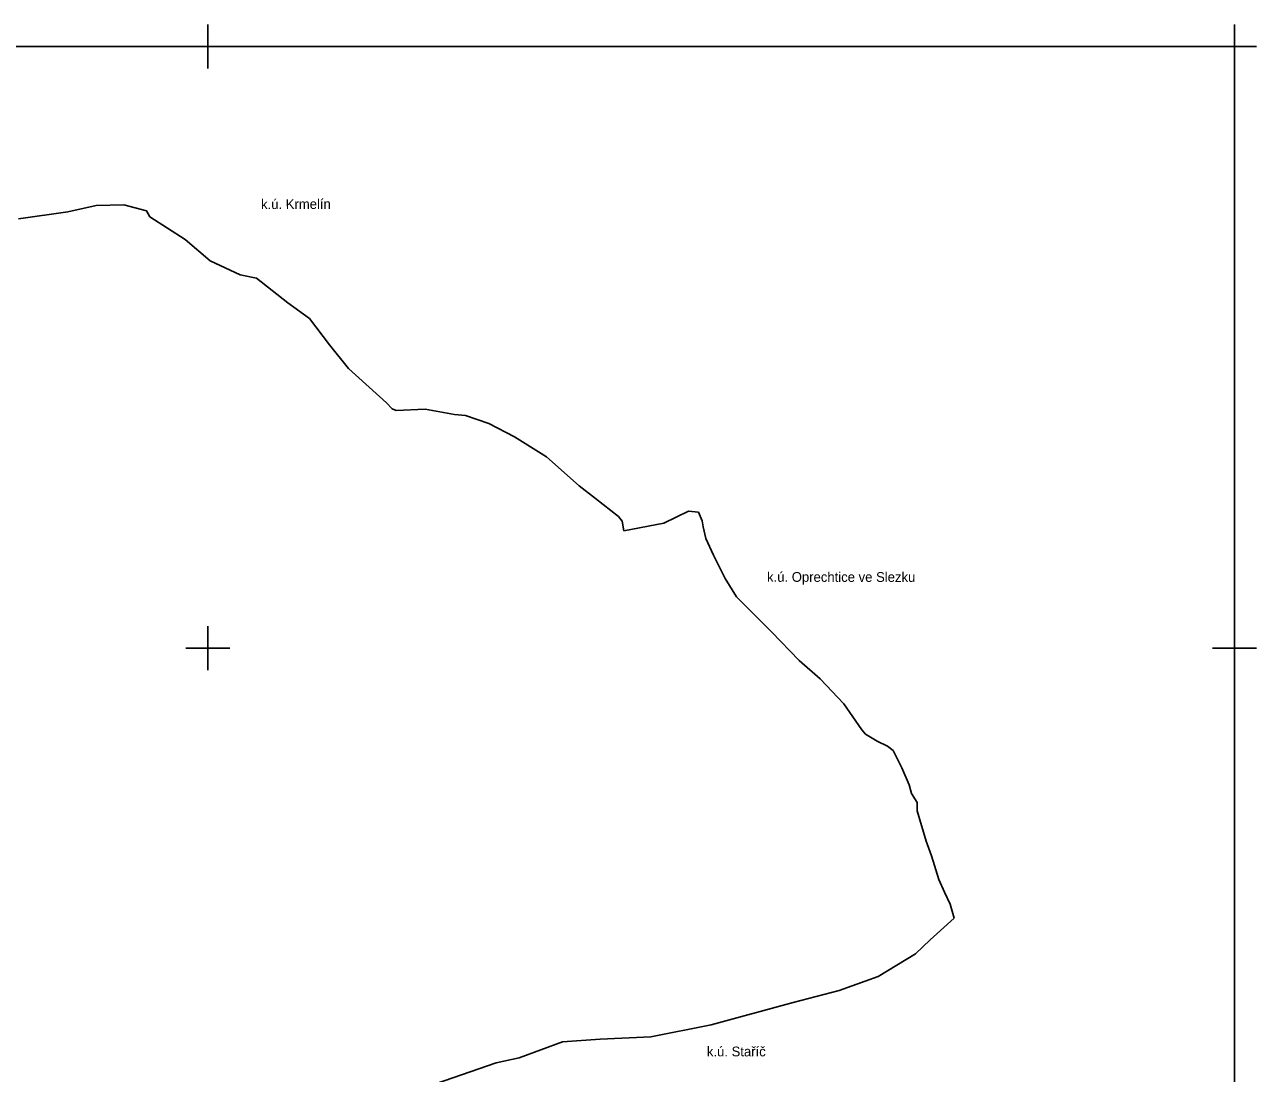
# Model space of a CAD drawing. Extents: x -478440 to -472455, y -1118045 to -1113755.
# Drawn here: x -474975 to -472455, y -1115900 to -1113755 of the extents above; entities that cross this region are included whole.
import ezdxf

# ---------------------------------------------------------------- set-up
doc = ezdxf.new("R2010")
doc.units = 0
for name, color, linetype in [('hranice kú', 7, 'Continuous'), ('Implicitní', 7, 'Continuous'), ('ObPÚ', 7, 'Continuous'), ('okolní k_ú_', 7, 'Continuous')]:
    doc.layers.add(name, color=color, linetype=linetype)

msp = doc.modelspace()

# ---------------------------------------------------------------- linework, layer by layer
at = {"layer": 'hranice kú'}
for p, q in [((-474886, -1114137.7), (-474987.2, -1114152.5)), ((-474828.5, -1114124.9), (-474886, -1114137.7)), ((-474772, -1114123.9), (-474828.5, -1114124.9)), ((-474725.6, -1114136), (-474772, -1114123.9)), ((-474718.2, -1114148.1), (-474725.6, -1114136)), ((-474646.3, -1114194.8), (-474718.2, -1114148.1)), ((-474595.2, -1114238.2), (-474646.3, -1114194.8)), ((-474533.5, -1114266.7), (-474595.2, -1114238.2)), ((-474500.2, -1114273.4), (-474533.5, -1114266.7)), ((-474436, -1114323.8), (-474500.2, -1114273.4)), ((-474392.1, -1114355.8), (-474436, -1114323.8)), ((-474351.1, -1114410.2), (-474392.1, -1114355.8)), ((-474312.1, -1114458.1), (-474351.1, -1114410.2)), ((-474234.1, -1114528.4), (-474312.1, -1114458.1)), ((-474222.7, -1114541.2), (-474234.1, -1114528.4)), ((-474214.6, -1114544.2), (-474222.7, -1114541.2)), ((-474155.1, -1114541.5), (-474214.6, -1114544.2)), ((-474095.2, -1114552.2), (-474155.1, -1114541.5)), ((-474072.7, -1114554.2), (-474095.2, -1114552.2)), ((-474025.3, -1114571.1), (-474072.7, -1114554.2)), ((-473972.5, -1114598), (-474025.3, -1114571.1)), ((-473907.3, -1114639), (-473972.5, -1114598)), ((-473840.6, -1114698.6), (-473907.3, -1114639)), ((-473807, -1114724.1), (-473840.6, -1114698.6)), ((-473760, -1114761.1), (-473807, -1114724.1)), ((-473752.6, -1114770.7), (-473760, -1114761.1)), ((-473616.5, -1114749.9), (-473666.9, -1114774.4)), ((-473595.9, -1114752.2), (-473616.5, -1114749.9)), ((-473588.6, -1114770.3), (-473595.9, -1114752.2)), ((-473748.8, -1114790.3), (-473752.6, -1114770.7)), ((-473666.9, -1114774.4), (-473748.8, -1114790.3)), ((-473587, -1114782.1), (-473588.6, -1114770.3)), ((-473581.1, -1114806.2), (-473587, -1114782.1)), ((-473565.4, -1114840.2), (-473581.1, -1114806.2)), ((-473541.9, -1114887.9), (-473565.4, -1114840.2)), ((-473518.4, -1114925.3), (-473541.9, -1114887.9)), ((-473447.1, -1114996.9), (-473518.4, -1114925.3)), ((-473390.3, -1115055.8), (-473447.1, -1114996.9)), ((-473347.2, -1115093.3), (-473390.3, -1115055.8)), ((-473299.1, -1115144.4), (-473347.2, -1115093.3)), ((-473261.8, -1115197.2), (-473299.1, -1115144.4)), ((-473254.4, -1115206.6), (-473261.8, -1115197.2)), ((-473230.6, -1115220.7), (-473254.4, -1115206.6)), ((-473209.4, -1115230.8), (-473230.6, -1115220.7)), ((-473197.9, -1115239.5), (-473209.4, -1115230.8)), ((-473191.9, -1115251.7), (-473197.9, -1115239.5)), ((-473180.1, -1115275.5), (-473191.9, -1115251.7)), ((-473165, -1115309.9), (-473180.1, -1115275.5)), ((-473160.6, -1115327.4), (-473165, -1115309.9)), ((-473148.9, -1115345.9), (-473160.6, -1115327.4)), ((-473149.2, -1115363.1), (-473148.9, -1115345.9)), ((-473130.7, -1115424.9), (-473149.2, -1115363.1)), ((-473119.6, -1115455.5), (-473130.7, -1115424.9)), ((-473104.5, -1115503.7), (-473119.6, -1115455.5)), ((-473092.7, -1115529.3), (-473104.5, -1115503.7)), ((-473081.3, -1115554.2), (-473092.7, -1115529.3)), ((-473073.6, -1115582.8), (-473081.3, -1115554.2)), ((-473122.6, -1115627.2), (-473073.6, -1115582.8)), ((-473152.2, -1115655.7), (-473122.6, -1115627.2)), ((-473228.9, -1115701.8), (-473152.2, -1115655.7)), ((-473308.3, -1115730.5), (-473228.9, -1115701.8)), ((-473402.8, -1115755.4), (-473308.3, -1115730.5)), ((-473570.6, -1115801.1), (-473402.8, -1115755.4)), ((-473693.7, -1115825.7), (-473570.6, -1115801.1)), ((-473797.2, -1115830.4), (-473693.7, -1115825.7)), ((-473963.2, -1115868.4), (-473874.4, -1115835.4)), ((-473874.4, -1115835.4), (-473797.2, -1115830.4)), ((-474010.2, -1115878.5), (-473963.2, -1115868.4)), ((-474134.2, -1115921.7), (-474010.2, -1115878.5))]:
    msp.add_line(p, q, dxfattribs=at)
at = {"layer": 'Implicitní'}
for p, q in [((-474600.1, -1113755.1), (-474600.1, -1113845.1)), ((-474600.1, -1113755.1), (-474600.1, -1113845.1)), ((-474600.1, -1113755.1), (-474600.1, -1113845.1)), ((-474600.1, -1113755.1), (-474600.1, -1113845.1)), ((-474600.1, -1113755.1), (-474600.1, -1113845.1)), ((-474600.1, -1113755.1), (-474600.1, -1113845.1)), ((-474600.1, -1113755.1), (-474600.1, -1113845.1)), ((-474600.1, -1113755.1), (-474600.1, -1113845.1)), ((-474600.1, -1113755.1), (-474600.1, -1113845.1)), ((-474600.1, -1113755.1), (-474600.1, -1113845.1)), ((-474600.1, -1113755.1), (-474600.1, -1113845.1)), ((-474600.1, -1113755.1), (-474600.1, -1113845.1)), ((-472500.1, -1113755.1), (-472500.1, -1113845.1)), ((-472500.1, -1113755.1), (-472500.1, -1113845.1)), ((-472500.1, -1113755.1), (-472500.1, -1113845.1)), ((-472500.1, -1113755.1), (-472500.1, -1113845.1)), ((-474555.1, -1113800.1), (-474645.1, -1113800.1)), ((-474555.1, -1113800.1), (-474645.1, -1113800.1)), ((-474555.1, -1113800.1), (-474645.1, -1113800.1)), ((-474555.1, -1113800.1), (-474645.1, -1113800.1)), ((-474555.1, -1113800.1), (-474645.1, -1113800.1)), ((-474555.1, -1113800.1), (-474645.1, -1113800.1)), ((-474555.1, -1113800.1), (-474645.1, -1113800.1)), ((-474555.1, -1113800.1), (-474645.1, -1113800.1)), ((-474555.1, -1113800.1), (-474645.1, -1113800.1)), ((-474555.1, -1113800.1), (-474645.1, -1113800.1)), ((-474555.1, -1113800.1), (-474645.1, -1113800.1)), ((-474555.1, -1113800.1), (-474645.1, -1113800.1)), ((-472455.1, -1113800.1), (-472545.1, -1113800.1)), ((-472455.1, -1113800.1), (-472545.1, -1113800.1)), ((-472455.1, -1113800.1), (-472545.1, -1113800.1)), ((-472455.1, -1113800.1), (-472545.1, -1113800.1)), ((-474600.1, -1114985.1), (-474600.1, -1115075.1)), ((-474600.1, -1114985.1), (-474600.1, -1115075.1)), ((-474600.1, -1114985.1), (-474600.1, -1115075.1)), ((-474600.1, -1114985.1), (-474600.1, -1115075.1)), ((-474600.1, -1114985.1), (-474600.1, -1115075.1)), ((-474600.1, -1114985.1), (-474600.1, -1115075.1)), ((-474600.1, -1114985.1), (-474600.1, -1115075.1)), ((-474600.1, -1114985.1), (-474600.1, -1115075.1)), ((-474600.1, -1114985.1), (-474600.1, -1115075.1)), ((-474600.1, -1114985.1), (-474600.1, -1115075.1)), ((-474600.1, -1114985.1), (-474600.1, -1115075.1)), ((-474600.1, -1114985.1), (-474600.1, -1115075.1)), ((-474600.1, -1114985.1), (-474600.1, -1115075.1)), ((-474600.1, -1114985.1), (-474600.1, -1115075.1)), ((-474600.1, -1114985.1), (-474600.1, -1115075.1)), ((-474600.1, -1114985.1), (-474600.1, -1115075.1)), ((-474600.1, -1114985.1), (-474600.1, -1115075.1)), ((-474600.1, -1114985.1), (-474600.1, -1115075.1)), ((-474600.1, -1114985.1), (-474600.1, -1115075.1)), ((-474600.1, -1114985.1), (-474600.1, -1115075.1)), ((-472500.1, -1114985.1), (-472500.1, -1115075.1)), ((-472500.1, -1114985.1), (-472500.1, -1115075.1)), ((-472500.1, -1114985.1), (-472500.1, -1115075.1)), ((-472500.1, -1114985.1), (-472500.1, -1115075.1)), ((-472500.1, -1114985.1), (-472500.1, -1115075.1)), ((-472500.1, -1114985.1), (-472500.1, -1115075.1)), ((-472500.1, -1114985.1), (-472500.1, -1115075.1)), ((-472500.1, -1114985.1), (-472500.1, -1115075.1)), ((-472500.1, -1114985.1), (-472500.1, -1115075.1)), ((-472500.1, -1114985.1), (-472500.1, -1115075.1)), ((-474555.1, -1115030.1), (-474645.1, -1115030.1)), ((-474555.1, -1115030.1), (-474645.1, -1115030.1)), ((-474555.1, -1115030.1), (-474645.1, -1115030.1)), ((-474555.1, -1115030.1), (-474645.1, -1115030.1)), ((-474555.1, -1115030.1), (-474645.1, -1115030.1)), ((-474555.1, -1115030.1), (-474645.1, -1115030.1)), ((-474555.1, -1115030.1), (-474645.1, -1115030.1)), ((-474555.1, -1115030.1), (-474645.1, -1115030.1)), ((-474555.1, -1115030.1), (-474645.1, -1115030.1)), ((-474555.1, -1115030.1), (-474645.1, -1115030.1)), ((-474555.1, -1115030.1), (-474645.1, -1115030.1)), ((-474555.1, -1115030.1), (-474645.1, -1115030.1)), ((-474555.1, -1115030.1), (-474645.1, -1115030.1)), ((-474555.1, -1115030.1), (-474645.1, -1115030.1)), ((-474555.1, -1115030.1), (-474645.1, -1115030.1)), ((-474555.1, -1115030.1), (-474645.1, -1115030.1)), ((-474555.1, -1115030.1), (-474645.1, -1115030.1)), ((-474555.1, -1115030.1), (-474645.1, -1115030.1)), ((-474555.1, -1115030.1), (-474645.1, -1115030.1)), ((-474555.1, -1115030.1), (-474645.1, -1115030.1)), ((-472455.1, -1115030.1), (-472545.1, -1115030.1)), ((-472455.1, -1115030.1), (-472545.1, -1115030.1)), ((-472455.1, -1115030.1), (-472545.1, -1115030.1)), ((-472455.1, -1115030.1), (-472545.1, -1115030.1)), ((-472455.1, -1115030.1), (-472545.1, -1115030.1)), ((-472455.1, -1115030.1), (-472545.1, -1115030.1)), ((-472455.1, -1115030.1), (-472545.1, -1115030.1)), ((-472455.1, -1115030.1), (-472545.1, -1115030.1)), ((-472455.1, -1115030.1), (-472545.1, -1115030.1)), ((-472455.1, -1115030.1), (-472545.1, -1115030.1))]:
    msp.add_line(p, q, dxfattribs=at)
msp.add_lwpolyline([(-478440.1, -1118000.1), (-472500.1, -1118000.1), (-472500.1, -1113800.1), (-478440.1, -1113800.1)], close=True, dxfattribs=at)
at = {"layer": 'ObPÚ'}
for p, q in [((-474886, -1114137.7), (-474987.2, -1114152.5)), ((-474828.5, -1114124.9), (-474886, -1114137.7)), ((-474772, -1114123.9), (-474828.5, -1114124.9)), ((-474725.6, -1114136), (-474772, -1114123.9)), ((-474718.2, -1114148.1), (-474725.6, -1114136)), ((-474646.3, -1114194.8), (-474718.2, -1114148.1)), ((-474595.2, -1114238.2), (-474646.3, -1114194.8)), ((-474533.5, -1114266.7), (-474595.2, -1114238.2)), ((-474500.2, -1114273.4), (-474533.5, -1114266.7)), ((-474436, -1114323.8), (-474500.2, -1114273.4)), ((-474392.1, -1114355.8), (-474436, -1114323.8)), ((-474351.1, -1114410.2), (-474392.1, -1114355.8)), ((-474312.1, -1114458.1), (-474351.1, -1114410.2)), ((-474234.1, -1114528.4), (-474312.1, -1114458.1)), ((-474222.7, -1114541.2), (-474234.1, -1114528.4)), ((-474214.6, -1114544.2), (-474222.7, -1114541.2)), ((-474155.1, -1114541.5), (-474214.6, -1114544.2)), ((-474095.2, -1114552.2), (-474155.1, -1114541.5)), ((-474072.7, -1114554.2), (-474095.2, -1114552.2)), ((-474025.3, -1114571.1), (-474072.7, -1114554.2)), ((-473972.5, -1114598), (-474025.3, -1114571.1)), ((-473907.3, -1114639), (-473972.5, -1114598)), ((-473840.6, -1114698.6), (-473907.3, -1114639)), ((-473807, -1114724.1), (-473840.6, -1114698.6)), ((-473760, -1114761.1), (-473807, -1114724.1)), ((-473752.6, -1114770.7), (-473760, -1114761.1)), ((-473616.5, -1114749.9), (-473666.9, -1114774.4)), ((-473595.9, -1114752.2), (-473616.5, -1114749.9)), ((-473588.6, -1114770.3), (-473595.9, -1114752.2)), ((-473748.8, -1114790.3), (-473752.6, -1114770.7)), ((-473666.9, -1114774.4), (-473748.8, -1114790.3)), ((-473587, -1114782.1), (-473588.6, -1114770.3)), ((-473581.1, -1114806.2), (-473587, -1114782.1)), ((-473565.4, -1114840.2), (-473581.1, -1114806.2)), ((-473541.9, -1114887.9), (-473565.4, -1114840.2)), ((-473518.4, -1114925.3), (-473541.9, -1114887.9)), ((-473447.1, -1114996.9), (-473518.4, -1114925.3)), ((-473390.3, -1115055.8), (-473447.1, -1114996.9)), ((-473347.2, -1115093.3), (-473390.3, -1115055.8)), ((-473299.1, -1115144.4), (-473347.2, -1115093.3)), ((-473261.8, -1115197.2), (-473299.1, -1115144.4)), ((-473254.4, -1115206.6), (-473261.8, -1115197.2)), ((-473230.6, -1115220.7), (-473254.4, -1115206.6)), ((-473209.4, -1115230.8), (-473230.6, -1115220.7)), ((-473197.9, -1115239.5), (-473209.4, -1115230.8)), ((-473191.9, -1115251.7), (-473197.9, -1115239.5)), ((-473180.1, -1115275.5), (-473191.9, -1115251.7)), ((-473165, -1115309.9), (-473180.1, -1115275.5)), ((-473160.6, -1115327.4), (-473165, -1115309.9)), ((-473148.9, -1115345.9), (-473160.6, -1115327.4)), ((-473149.2, -1115363.1), (-473148.9, -1115345.9)), ((-473130.7, -1115424.9), (-473149.2, -1115363.1)), ((-473119.6, -1115455.5), (-473130.7, -1115424.9)), ((-473104.5, -1115503.7), (-473119.6, -1115455.5)), ((-473092.7, -1115529.3), (-473104.5, -1115503.7)), ((-473081.3, -1115554.2), (-473092.7, -1115529.3)), ((-473073.6, -1115582.8), (-473081.3, -1115554.2)), ((-473122.6, -1115627.2), (-473073.6, -1115582.8)), ((-473152.2, -1115655.7), (-473122.6, -1115627.2)), ((-473228.9, -1115701.8), (-473152.2, -1115655.7)), ((-473308.3, -1115730.5), (-473228.9, -1115701.8)), ((-473402.8, -1115755.4), (-473308.3, -1115730.5)), ((-473570.6, -1115801.1), (-473402.8, -1115755.4)), ((-473693.7, -1115825.7), (-473570.6, -1115801.1)), ((-473797.2, -1115830.4), (-473693.7, -1115825.7)), ((-473963.2, -1115868.4), (-473874.4, -1115835.4)), ((-473874.4, -1115835.4), (-473797.2, -1115830.4)), ((-474010.2, -1115878.5), (-473963.2, -1115868.4)), ((-474134.2, -1115921.7), (-474010.2, -1115878.5))]:
    msp.add_line(p, q, dxfattribs=at)

# ---------------------------------------------------------------- texts
at = {"layer": 'okolní k_ú_'}
for s, rotation, p in [('k.ú. Krmelín', 0.1596, (-474491, -1114132.3)), ('k.ú. Oprechtice ve Slezku', 359.9619, (-473456, -1114894.7)), ('k.ú. Staříč', 359.9619, (-473579.1, -1115865.3))]:
    msp.add_text(s, height=20, rotation=rotation, dxfattribs=at).set_placement(p)

doc.saveas('drawing.dxf')
